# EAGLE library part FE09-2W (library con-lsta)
FEMALE HEADER
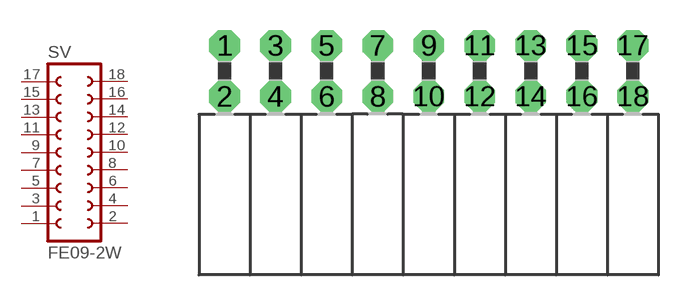
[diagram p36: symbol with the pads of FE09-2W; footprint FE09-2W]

Designator prefix SV

## FE09-2W (OC_FARNELL: unknown; OC_NEWARK: unknown)  [FE09-2W]
1  1  pas
2  2  pas
3  3  pas
4  4  pas
5  5  pas
6  6  pas
7  7  pas
8  8  pas
9  9  pas
10  10  pas
11  11  pas
12  12  pas
13  13  pas
14  14  pas
15  15  pas
16  16  pas
17  17  pas
18  18  pas

## Footprint FE09-2W (pad centres in mm)
FEMALE HEADER
drill 1.016 octagon: 1 -10.16,1.27; 2 -10.16,-1.27; 3 -7.62,1.27; 4 -7.62,-1.27; 5 -5.08,1.27; 6 -5.08,-1.27; 7 -2.54,1.27; 8 -2.54,-1.27; 9 0,1.27; 10 0,-1.27; 11 2.54,1.27; 12 2.54,-1.27; 13 5.08,1.27; 14 5.08,-1.27; 15 7.62,1.27; 16 7.62,-1.27; 17 10.16,1.27; 18 10.16,-1.27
